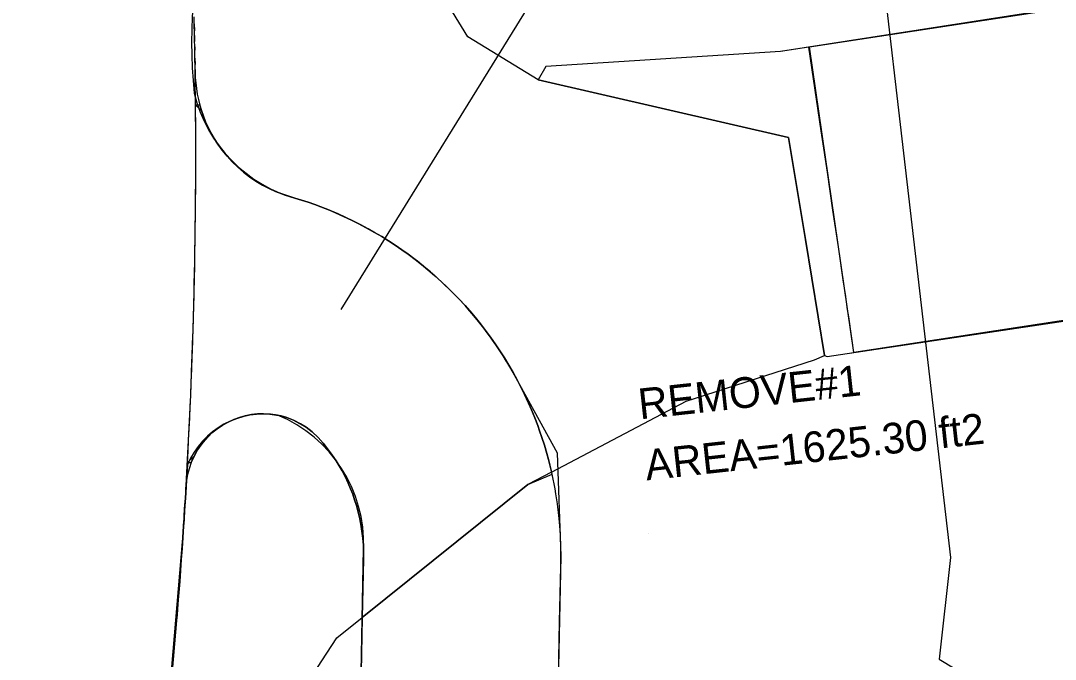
# Model space of a CAD drawing. Extents: x 1509538 to 1510847, y 401283 to 402022.
# Drawn here: x 1509791.8 to 1509886.2, y 401568.2 to 401626.4 of the extents above; entities that cross this region are included whole.
import ezdxf

# ---------------------------------------------------------------- set-up
doc = ezdxf.new("R2010")
doc.units = 0
for name, color, linetype in [('LAWE_P_T', 7, 'Continuous'), ('Level 10', 7, 'Continuous'), ('Level 2', 7, 'Continuous'), ('Level 24', 7, 'Continuous'), ('Level 25', 7, 'Continuous'), ('Level 3', 7, 'Continuous'), ('Level 4', 7, 'Continuous'), ('Level 7', 7, 'Continuous')]:
    doc.layers.add(name, color=color, linetype=linetype)

msp = doc.modelspace()

# ---------------------------------------------------------------- linework, layer by layer
at = {"layer": 'LAWE_P_T'}
msp.add_lwpolyline([(1509821.018, 401600.097), (1509839.911, 401630.638), (1509875.612, 401634.53)], dxfattribs=at)
at = {"layer": 'Level 10'}
for p, q in [((1509807.638, 401625.075), (1509807.629, 401625.503)), ((1509807.682, 401622.77), (1509807.678, 401622.994)), ((1509807.688, 401622.437), (1509807.682, 401622.77)), ((1509806.834, 401583.345), (1509806.875, 401584.042)), ((1509806.784, 401582.521), (1509806.834, 401583.345)), ((1509806.741, 401581.831), (1509806.784, 401582.521)), ((1509806.507, 401578.299), (1509806.576, 401579.308)), ((1509806.21, 401574.264), (1509806.287, 401575.273))]:
    msp.add_line(p, q, dxfattribs=at)
for points in [[(1509807.608, 401626.424), (1509807.603, 401626.611), (1509807.602, 401626.671), (1509807.6, 401626.79)], [(1509807.629, 401625.503), (1509807.622, 401625.803), (1509807.615, 401626.131)], [(1509807.65, 401624.522), (1509807.644, 401624.792), (1509807.638, 401625.075)], [(1509807.665, 401623.734), (1509807.664, 401623.781), (1509807.659, 401624.034)], [(1509807.698, 401621.744), (1509807.698, 401621.758), (1509807.695, 401621.97)], [(1509806.576, 401579.308), (1509806.644, 401580.317), (1509806.683, 401580.919), (1509806.741, 401581.831)], [(1509806.287, 401575.273), (1509806.362, 401576.281), (1509806.436, 401577.29), (1509806.507, 401578.299)], [(1509805.163, 401562.527), (1509805.605, 401567.117), (1509806.006, 401571.716), (1509806.049, 401572.248), (1509806.13, 401573.256), (1509806.21, 401574.264)]]:
    msp.add_lwpolyline(points, dxfattribs=at)
for start, end in [(1.33563, 1.36826), (1.10226, 1.15664), (0.98655, 1.06893), (0.87262, 0.92459), (356.65108, 0.84746)]:
    msp.add_arc((1509292.755, 401614.126), 515, start, end, dxfattribs=at)
at = {"layer": 'Level 2'}
for p, q in [((1509807.682, 401622.77), (1509807.678, 401622.994)), ((1509808.276, 401618.223), (1509807.734, 401618.725)), ((1509808.276, 401618.223), (1509808.125, 401618.728)), ((1509808.881, 401616.708), (1509808.652, 401617.213)), ((1509809.139, 401616.202), (1509808.881, 401616.708)), ((1509810.172, 401614.606), (1509809.764, 401615.171)), ((1509812.108, 401612.608), (1509811.082, 401613.551)), ((1509811.581, 401613.065), (1509811.082, 401613.551)), ((1509812.108, 401612.608), (1509811.581, 401613.065)), ((1509812.661, 401612.184), (1509812.108, 401612.608)), ((1509812.661, 401612.184), (1509812.108, 401612.608)), ((1509813.237, 401611.791), (1509812.661, 401612.184)), ((1509813.835, 401611.433), (1509813.237, 401611.791)), ((1509814.458, 401611.108), (1509813.835, 401611.433)), ((1509814.458, 401611.108), (1509813.835, 401611.433)), ((1509816.804, 401610.248), (1509815.607, 401610.622)), ((1509818.626, 401609.647), (1509818.018, 401609.86)), ((1509819.152, 401609.452), (1509818.626, 401609.647)), ((1509819.94, 401609.141), (1509819.152, 401609.452)), ((1509820.504, 401608.904), (1509819.94, 401609.141)), ((1509825.01, 401606.55), (1509825.01, 401606.551)), ((1509828.931, 401603.712), (1509828.34, 401604.197)), ((1509835.504, 401596.313), (1509835.078, 401596.947)), ((1509835.916, 401595.67), (1509835.504, 401596.313)), ((1509838.379, 401590.929), (1509838.105, 401591.559)), ((1509812.275, 401590.397), (1509812.826, 401590.502)), ((1509813.946, 401590.578), (1509814.498, 401590.55)), ((1509814.498, 401590.55), (1509815.532, 401590.376)), ((1509815.027, 401590.481), (1509815.532, 401590.376)), ((1509816.672, 401589.989), (1509817.811, 401589.357)), ((1509817.3, 401589.675), (1509817.811, 401589.357)), ((1509817.811, 401589.357), (1509818.376, 401588.928)), ((1509809.227, 401588.826), (1509809.694, 401589.204)), ((1509839.558, 401587.7), (1509839.324, 401588.428)), ((1509840.256, 401585.071), (1509839.931, 401586.401)), ((1509840.256, 401585.071), (1509839.931, 401586.401)), ((1509838.036, 401584.113), (1509840.256, 401585.071)), ((1509838.036, 401584.113), (1509840.256, 401585.071)), ((1509806.834, 401583.345), (1509806.875, 401584.042)), ((1509822.948, 401571.989), (1509838.036, 401584.113)), ((1509822.948, 401571.989), (1509838.036, 401584.113)), ((1509806.784, 401582.521), (1509806.834, 401583.345)), ((1509806.741, 401581.831), (1509806.784, 401582.521)), ((1509822.687, 401581.153), (1509822.852, 401580.31)), ((1509822.852, 401580.31), (1509822.993, 401579.245)), ((1509806.507, 401578.299), (1509806.576, 401579.308)), ((1509822.993, 401579.245), (1509823.044, 401578.603)), ((1509849.096, 401579.657), (1509849.096, 401579.657)), ((1509823.044, 401578.603), (1509823.068, 401577.959)), ((1509806.21, 401574.264), (1509806.287, 401575.273))]:
    msp.add_line(p, q, dxfattribs=at)
for points in [[(1509807.608, 401626.424), (1509807.603, 401626.611)], [(1509807.629, 401625.503), (1509807.622, 401625.803), (1509807.615, 401626.131)], [(1509807.629, 401625.503), (1509807.622, 401625.803), (1509807.615, 401626.131)], [(1509807.638, 401625.075), (1509807.629, 401625.503)], [(1509807.65, 401624.522), (1509807.644, 401624.792), (1509807.638, 401625.075)], [(1509807.65, 401624.522), (1509807.644, 401624.792), (1509807.638, 401625.075)], [(1509807.665, 401623.734), (1509807.664, 401623.781), (1509807.659, 401624.034)], [(1509807.665, 401623.734), (1509807.664, 401623.781), (1509807.659, 401624.034)], [(1509807.688, 401622.437), (1509807.682, 401622.77), (1509807.678, 401622.994)], [(1509807.688, 401622.437), (1509807.682, 401622.77)], [(1509807.698, 401621.744), (1509807.698, 401621.758), (1509807.695, 401621.97)], [(1509807.698, 401621.744), (1509807.698, 401621.758), (1509807.695, 401621.97)], [(1509808.125, 401618.728), (1509807.734, 401618.725)], [(1509808.881, 401616.708), (1509808.652, 401617.213), (1509808.451, 401617.718), (1509808.276, 401618.223)], [(1509808.652, 401617.213), (1509808.451, 401617.718), (1509808.276, 401618.223)], [(1509811.082, 401613.551), (1509810.611, 401614.065), (1509810.172, 401614.606), (1509809.764, 401615.171), (1509809.428, 401615.696), (1509809.139, 401616.202), (1509808.881, 401616.708)], [(1509809.764, 401615.171), (1509809.428, 401615.696), (1509809.139, 401616.202)], [(1509811.082, 401613.551), (1509810.611, 401614.065), (1509810.172, 401614.606)], [(1509813.835, 401611.433), (1509813.237, 401611.791), (1509812.661, 401612.184)], [(1509815.607, 401610.622), (1509815.027, 401610.85), (1509814.458, 401611.108)], [(1509815.607, 401610.622), (1509815.027, 401610.85), (1509814.458, 401611.108)], [(1509839.931, 401586.401), (1509839.775, 401586.968), (1509839.558, 401587.7), (1509839.324, 401588.428), (1509838.943, 401589.509), (1509838.669, 401590.222), (1509838.379, 401590.929), (1509838.105, 401591.559), (1509837.752, 401592.322), (1509837.415, 401593.008), (1509837.063, 401593.686), (1509836.695, 401594.355), (1509836.313, 401595.017), (1509835.916, 401595.67), (1509835.504, 401596.313), (1509835.078, 401596.947), (1509834.7, 401597.486), (1509834.184, 401598.186), (1509833.716, 401598.79), (1509833.235, 401599.384), (1509832.324, 401600.437), (1509831.716, 401601.093), (1509831.18, 401601.645), (1509830.178, 401602.612), (1509829.572, 401603.16), (1509828.931, 401603.712), (1509828.34, 401604.197), (1509827.776, 401604.639), (1509827.127, 401605.126), (1509826.546, 401605.54), (1509825.95, 401605.948), (1509825.322, 401606.357), (1509824.722, 401606.73), (1509824.072, 401607.115), (1509823.31, 401607.542), (1509822.578, 401607.928), (1509822.025, 401608.205), (1509821.246, 401608.575), (1509820.504, 401608.904), (1509819.94, 401609.141), (1509819.152, 401609.452), (1509818.626, 401609.647), (1509818.018, 401609.86), (1509817.41, 401610.06), (1509816.804, 401610.248), (1509815.607, 401610.622)], [(1509818.018, 401609.86), (1509817.41, 401610.06), (1509816.804, 401610.248)], [(1509824.072, 401607.115), (1509823.31, 401607.542), (1509822.578, 401607.928), (1509822.025, 401608.205), (1509821.246, 401608.575), (1509820.504, 401608.904)], [(1509825.01, 401606.551), (1509824.722, 401606.73), (1509824.072, 401607.115)], [(1509825.322, 401606.357), (1509825.01, 401606.55)], [(1509828.34, 401604.197), (1509827.776, 401604.639), (1509827.127, 401605.126), (1509826.546, 401605.54), (1509825.95, 401605.948), (1509825.322, 401606.357)], [(1509830.178, 401602.612), (1509829.572, 401603.16), (1509828.931, 401603.712)], [(1509831.18, 401601.645), (1509830.661, 401602.146), (1509830.178, 401602.612)], [(1509832.324, 401600.437), (1509831.716, 401601.093), (1509831.18, 401601.645)], [(1509833.235, 401599.384), (1509832.735, 401599.962), (1509832.324, 401600.437)], [(1509835.078, 401596.947), (1509834.7, 401597.486), (1509834.184, 401598.186), (1509833.716, 401598.79), (1509833.235, 401599.384)], [(1509836.695, 401594.355), (1509836.313, 401595.017), (1509835.916, 401595.67)], [(1509837.415, 401593.008), (1509837.063, 401593.686), (1509836.695, 401594.355)], [(1509838.105, 401591.559), (1509837.752, 401592.322), (1509837.415, 401593.008)], [(1509809.694, 401589.204), (1509810.199, 401589.545), (1509810.702, 401589.826), (1509811.22, 401590.062), (1509811.733, 401590.248), (1509812.275, 401590.397), (1509812.826, 401590.502), (1509813.385, 401590.563), (1509813.946, 401590.578), (1509814.498, 401590.55), (1509815.027, 401590.481)], [(1509809.694, 401589.204), (1509810.199, 401589.545), (1509810.702, 401589.826), (1509811.22, 401590.062), (1509811.733, 401590.248), (1509812.275, 401590.397)], [(1509812.826, 401590.502), (1509813.385, 401590.563), (1509813.946, 401590.578)], [(1509815.532, 401590.376), (1509816.064, 401590.223), (1509816.672, 401589.989), (1509817.3, 401589.675)], [(1509815.532, 401590.376), (1509816.064, 401590.223), (1509816.672, 401589.989)], [(1509839.324, 401588.428), (1509839.117, 401589.015), (1509838.943, 401589.509), (1509838.669, 401590.222), (1509838.379, 401590.929)], [(1509817.811, 401589.357), (1509818.376, 401588.928), (1509818.908, 401588.428), (1509819.383, 401587.889), (1509820.148, 401586.89), (1509820.549, 401586.293), (1509821.102, 401585.36), (1509821.4, 401584.789), (1509821.873, 401583.744), (1509822.07, 401583.241), (1509822.249, 401582.733), (1509822.411, 401582.218), (1509822.687, 401581.153), (1509822.852, 401580.31), (1509822.993, 401579.245), (1509823.044, 401578.603), (1509823.068, 401577.959), (1509823.067, 401577.315), (1509822.948, 401571.989)], [(1509807.339, 401586.122), (1509807.602, 401586.715), (1509807.92, 401587.282), (1509808.297, 401587.827), (1509809.227, 401588.826)], [(1509807.92, 401587.282), (1509808.297, 401587.827), (1509808.761, 401588.374), (1509809.227, 401588.826)], [(1509809.227, 401588.826), (1509809.694, 401589.204)], [(1509818.376, 401588.928), (1509818.908, 401588.428), (1509819.383, 401587.889)], [(1509819.383, 401587.889), (1509820.148, 401586.89), (1509820.832, 401585.834), (1509821.102, 401585.36), (1509821.4, 401584.789)], [(1509839.931, 401586.401), (1509839.775, 401586.968), (1509839.558, 401587.7)], [(1509806.994, 401586.141), (1509807.602, 401586.715), (1509807.92, 401587.282)], [(1509806.994, 401586.141), (1509807.339, 401586.122)], [(1509821.4, 401584.789), (1509821.66, 401584.239), (1509821.873, 401583.744)], [(1509805.605, 401567.119), (1509806.006, 401571.716), (1509806.049, 401572.248), (1509806.09, 401572.752), (1509806.13, 401573.256), (1509806.17, 401573.76), (1509806.21, 401574.264), (1509806.249, 401574.768), (1509806.287, 401575.273), (1509806.325, 401575.777), (1509806.362, 401576.281), (1509806.365, 401576.316), (1509806.399, 401576.786), (1509806.436, 401577.29), (1509806.442, 401577.383), (1509806.472, 401577.794), (1509806.507, 401578.299), (1509806.542, 401578.803), (1509806.576, 401579.308), (1509806.61, 401579.812), (1509806.644, 401580.317), (1509806.677, 401580.822), (1509806.683, 401580.919), (1509806.709, 401581.326), (1509806.741, 401581.831), (1509806.773, 401582.336), (1509806.784, 401582.521), (1509806.804, 401582.84), (1509806.834, 401583.345), (1509806.864, 401583.85), (1509806.872, 401583.988), (1509806.875, 401584.042)], [(1509821.873, 401583.744), (1509822.07, 401583.241), (1509822.249, 401582.733), (1509822.411, 401582.218), (1509822.687, 401581.153)], [(1509806.576, 401579.308), (1509806.644, 401580.317), (1509806.683, 401580.919), (1509806.741, 401581.831)], [(1509849.096, 401579.657), (1509849.096, 401579.657)], [(1509806.287, 401575.273), (1509806.362, 401576.281), (1509806.436, 401577.29), (1509806.507, 401578.299)], [(1509823.068, 401577.959), (1509823.067, 401577.315), (1509822.948, 401571.989)], [(1509805.163, 401562.527), (1509805.605, 401567.117), (1509806.006, 401571.716), (1509806.049, 401572.248), (1509806.13, 401573.256), (1509806.21, 401574.264)]]:
    msp.add_lwpolyline(points, dxfattribs=at)
for start, end in [(1.33563, 1.36826), (1.33563, 1.36826), (1.21817, 1.26581), (1.10226, 1.15664), (1.10226, 1.15664), (0.98655, 1.06893), (0.98655, 1.06893), (0.87262, 0.92459), (0.87262, 0.92459), (356.65108, 0.84746), (356.65108, 0.84746), (356.88495, 0.51156), (356.88495, 0.51156)]:
    msp.add_arc((1509292.755, 401614.126), 515, start, end, dxfattribs=at)
at = {"layer": 'Level 24'}
msp.add_lwpolyline([(1509829.75, 401765.911), (1509866.097, 401667.732), (1509876.615, 401577.466), (1509875.566, 401568.188), (1509883.853, 401563.183), (1509866.769, 401506.877), (1509856.531, 401476.729), (1509809.074, 401412), (1509809.101, 401403.538), (1509796.557, 401386.395), (1509783.485, 401379.525), (1509778.168, 401371.598), (1509774.096, 401368.359), (1509767.585, 401349.346), (1509764.231, 401344.649), (1509737.941, 401349.46)], dxfattribs=at)
at = {"layer": 'Level 25'}
msp.add_lwpolyline([(1510026.788, 401648.904), (1510037.691, 401640.619), (1510051.798, 401629.899), (1510058.051, 401624.503), (1509984.136, 401613.929), (1509867.795, 401596.154), (1509863.727, 401624.032)], close=True, dxfattribs=at)
at = {"layer": 'Level 3'}
for p, q in [((1509840.21, 401585.26), (1509838.036, 401584.113)), ((1509838.036, 401584.113), (1509822.948, 401571.989)), ((1509822.948, 401571.989), (1509822.838, 401567.017))]:
    msp.add_line(p, q, dxfattribs=at)
msp.add_lwpolyline([(1509840.833, 401566.616), (1509840.944, 401571.615), (1509841.056, 401576.614), (1509841.062, 401576.914), (1509841.065, 401578.283), (1509841.013, 401579.652), (1509840.906, 401581.017), (1509840.744, 401582.376), (1509840.605, 401583.28), (1509840.527, 401583.728), (1509840.256, 401585.071), (1509840.21, 401585.26)], dxfattribs=at)
at = {"layer": 'Level 4'}
for p, q in [((1509807.615, 401626.131), (1509807.629, 401625.503)), ((1509807.638, 401625.075), (1509807.65, 401624.522)), ((1509863.686, 401624.025), (1509861.081, 401623.62)), ((1509864.815, 401616.369), (1509863.686, 401624.025)), ((1509807.678, 401622.994), (1509807.688, 401622.437)), ((1509807.695, 401621.97), (1509807.699, 401621.728)), ((1509807.715, 401621.253), (1509807.753, 401620.748)), ((1509807.753, 401620.748), (1509807.813, 401620.243)), ((1509807.998, 401619.233), (1509808.125, 401618.728)), ((1509808.125, 401618.728), (1509808.276, 401618.223)), ((1509861.826, 401615.769), (1509863.366, 401606.462)), ((1509861.826, 401615.769), (1509863.366, 401606.462)), ((1509865.369, 401612.611), (1509864.815, 401616.369)), ((1509811.082, 401613.551), (1509811.581, 401613.065)), ((1509811.581, 401613.065), (1509812.108, 401612.608)), ((1509812.108, 401612.608), (1509812.661, 401612.184)), ((1509865.878, 401609.154), (1509865.369, 401612.611)), ((1509813.835, 401611.433), (1509814.458, 401611.108)), ((1509866.373, 401605.798), (1509865.878, 401609.154)), ((1509863.366, 401606.462), (1509865.104, 401595.902)), ((1509863.366, 401606.462), (1509865.104, 401595.902)), ((1509866.531, 401604.727), (1509866.373, 401605.798)), ((1509866.69, 401603.647), (1509866.531, 401604.727)), ((1509866.848, 401602.576), (1509866.69, 401603.647)), ((1509867.009, 401601.482), (1509866.848, 401602.576)), ((1509867.215, 401600.085), (1509867.009, 401601.482)), ((1509867.215, 401600.085), (1509867.215, 401600.085)), ((1509865.104, 401595.902), (1509865.361, 401595.79)), ((1509865.104, 401595.902), (1509865.361, 401595.79)), ((1509839.931, 401586.401), (1509840.21, 401585.26)), ((1509820.637, 401570.132), (1509822.948, 401571.989)), ((1509822.948, 401571.989), (1509822.949, 401572.016)), ((1509812.343, 401557.623), (1509820.637, 401570.132))]:
    msp.add_line(p, q, dxfattribs=at)
for points in [[(1510068.151, 401655.21), (1510017.641, 401647.51), (1509967.631, 401640.04), (1509894.451, 401628.81), (1509861.081, 401623.62)], [(1509863.366, 401606.462), (1509861.826, 401615.769), (1509838.993, 401621.028), (1509832.572, 401624.959), (1509822.152, 401641.967), (1509818.648, 401651.093)], [(1509865.361, 401595.79), (1509909.051, 401602.33), (1509950.021, 401608.51), (1509992.391, 401615.24), (1510032.231, 401621.12), (1510071.841, 401626.31)], [(1509807.659, 401624.034), (1509807.665, 401623.734)], [(1509861.081, 401623.62), (1509839.684, 401622.259), (1509838.993, 401621.028), (1509861.826, 401615.769)], [(1509861.081, 401623.62), (1509839.684, 401622.259), (1509838.993, 401621.028), (1509861.826, 401615.769)], [(1509807.699, 401621.728), (1509807.715, 401621.253)], [(1509807.813, 401620.243), (1509807.895, 401619.738), (1509807.998, 401619.233)], [(1509808.276, 401618.223), (1509808.451, 401617.718), (1509808.652, 401617.213), (1509808.881, 401616.708)], [(1509808.881, 401616.708), (1509809.139, 401616.202), (1509809.428, 401615.696), (1509809.764, 401615.171), (1509810.172, 401614.606), (1509810.611, 401614.065), (1509811.082, 401613.551)], [(1509812.661, 401612.184), (1509813.237, 401611.791), (1509813.835, 401611.433)], [(1509814.458, 401611.108), (1509815.027, 401610.85), (1509815.607, 401610.622), (1509815.805, 401610.553)], [(1509815.805, 401610.553), (1509816.804, 401610.248), (1509817.41, 401610.06), (1509818.018, 401609.86), (1509818.626, 401609.647), (1509819.152, 401609.452), (1509819.94, 401609.141), (1509820.504, 401608.904), (1509821.246, 401608.575), (1509822.025, 401608.205), (1509822.578, 401607.928), (1509823.31, 401607.542), (1509824.072, 401607.115), (1509824.722, 401606.73), (1509825.322, 401606.357), (1509825.95, 401605.948), (1509826.546, 401605.54), (1509827.127, 401605.126), (1509827.776, 401604.639), (1509828.34, 401604.197), (1509828.931, 401603.712), (1509829.572, 401603.16), (1509830.178, 401602.612), (1509830.666, 401602.151), (1509831.18, 401601.645), (1509831.716, 401601.093), (1509832.324, 401600.437), (1509832.74, 401599.966), (1509833.235, 401599.384), (1509833.716, 401598.79), (1509834.184, 401598.186), (1509834.7, 401597.486), (1509835.078, 401596.947), (1509835.504, 401596.313), (1509835.916, 401595.67), (1509836.313, 401595.017), (1509836.695, 401594.355), (1509837.063, 401593.686), (1509837.415, 401593.008), (1509837.752, 401592.322), (1509838.105, 401591.559), (1509838.379, 401590.929), (1509838.669, 401590.222), (1509838.943, 401589.509), (1509839.122, 401589.017), (1509839.324, 401588.428), (1509839.558, 401587.7), (1509839.775, 401586.968), (1509839.931, 401586.401)], [(1509864.203, 401595.491), (1509865.104, 401595.902), (1509863.366, 401606.462)], [(1509865.361, 401595.79), (1509867.795, 401596.154), (1509867.602, 401597.464), (1509867.314, 401599.414), (1509867.215, 401600.085)], [(1509840.21, 401585.26), (1509852.478, 401591.736), (1509864.203, 401595.491)], [(1509815.027, 401590.481), (1509814.498, 401590.55), (1509813.946, 401590.578), (1509813.385, 401590.563), (1509812.826, 401590.502), (1509812.275, 401590.397), (1509811.733, 401590.248), (1509811.22, 401590.062), (1509810.702, 401589.826), (1509810.199, 401589.545), (1509809.694, 401589.204), (1509809.227, 401588.826)], [(1509815.532, 401590.376), (1509815.027, 401590.481)], [(1509817.3, 401589.675), (1509816.672, 401589.989), (1509816.064, 401590.223), (1509815.532, 401590.376)], [(1509817.811, 401589.357), (1509817.3, 401589.675)], [(1509822.949, 401572.016), (1509823.067, 401577.315), (1509823.068, 401577.959), (1509823.044, 401578.603), (1509822.993, 401579.245), (1509822.852, 401580.31), (1509822.815, 401580.521), (1509822.687, 401581.153), (1509822.411, 401582.218), (1509822.249, 401582.733), (1509822.07, 401583.241), (1509821.873, 401583.744), (1509821.66, 401584.239), (1509821.4, 401584.789), (1509821.102, 401585.36), (1509820.832, 401585.834), (1509820.549, 401586.293), (1509820.148, 401586.89), (1509819.83, 401587.325), (1509819.383, 401587.889), (1509818.908, 401588.428), (1509818.376, 401588.928), (1509817.811, 401589.357)], [(1509809.227, 401588.826), (1509808.761, 401588.374), (1509808.297, 401587.827), (1509807.92, 401587.282), (1509807.602, 401586.715), (1509807.339, 401586.122), (1509807.148, 401585.564), (1509807.013, 401585.034), (1509806.924, 401584.52), (1509806.918, 401584.473)], [(1509806.872, 401583.988), (1509806.834, 401583.345), (1509806.784, 401582.521), (1509806.741, 401581.831), (1509806.683, 401580.919), (1509806.644, 401580.317), (1509806.576, 401579.308), (1509806.507, 401578.299), (1509806.436, 401577.29), (1509806.362, 401576.281), (1509806.287, 401575.273), (1509806.21, 401574.264), (1509806.13, 401573.256), (1509806.049, 401572.248), (1509806.006, 401571.716), (1509805.605, 401567.117)], [(1509806.918, 401584.473), (1509806.872, 401583.988)]]:
    msp.add_lwpolyline(points, dxfattribs=at)
for start, end in [(1.33563, 1.36826), (1.21817, 1.26581), (1.10226, 1.15664), (0.98655, 1.06893), (0.87262, 0.92459)]:
    msp.add_arc((1509292.755, 401614.126), 515, start, end, dxfattribs=at)
at = {"layer": 'Level 7'}
for p, q in [((1509836.115, 401595.344), (1509840.733, 401587.013)), ((1509836.115, 401595.344), (1509840.733, 401587.013)), ((1509840.733, 401587.013), (1509841.063, 401577.599)), ((1509840.733, 401587.013), (1509841.063, 401577.599)), ((1509806.988, 401585.934), (1509806.644, 401580.317)), ((1509806.988, 401585.934), (1509806.644, 401580.317)), ((1509806.644, 401580.317), (1509804.895, 401559.964)), ((1509806.644, 401580.317), (1509804.895, 401559.964)), ((1509822.838, 401567.017), (1509823.056, 401578.281)), ((1509822.838, 401567.017), (1509823.056, 401578.281)), ((1509841.063, 401577.599), (1509840.275, 401541.562)), ((1509841.063, 401577.599), (1509840.275, 401541.562))]:
    msp.add_line(p, q, dxfattribs=at)
for centre, radius, start, end in [((1509851.69, 401624.482), 44.318, 162.01319, 186.05412), ((1509851.69, 401624.482), 44.318, 162.01319, 186.05412), ((1509820.449, 401622.928), 13.204, 193.66882, 255.3377), ((1509820.449, 401622.928), 13.204, 193.66882, 255.3377), ((1509807.07, 401577.671), 33.998, 31.31935, 72.82974), ((1509807.07, 401577.671), 33.998, 31.31935, 72.82974), ((1509813.983, 401582.946), 7.607, 80.60206, 156.8715), ((1509813.983, 401582.946), 7.607, 80.60206, 156.8715), ((1509810.439, 401578.767), 12.627, 357.79546, 67.72366), ((1509810.439, 401578.767), 12.627, 357.79546, 67.72366)]:
    msp.add_arc(centre, radius, start, end, dxfattribs=at)

# ---------------------------------------------------------------- texts
at = {"layer": 'LAWE_P_T'}
for s, height, p in [('REMOVE#1', 2.8, (1509848.274, 401590.062)), ('AREA=1625.30 ft2', 2.79999, (1509848.881, 401584.495))]:
    msp.add_text(s, height=height, rotation=6.2219, dxfattribs=at).set_placement(p)

doc.saveas('drawing.dxf')
